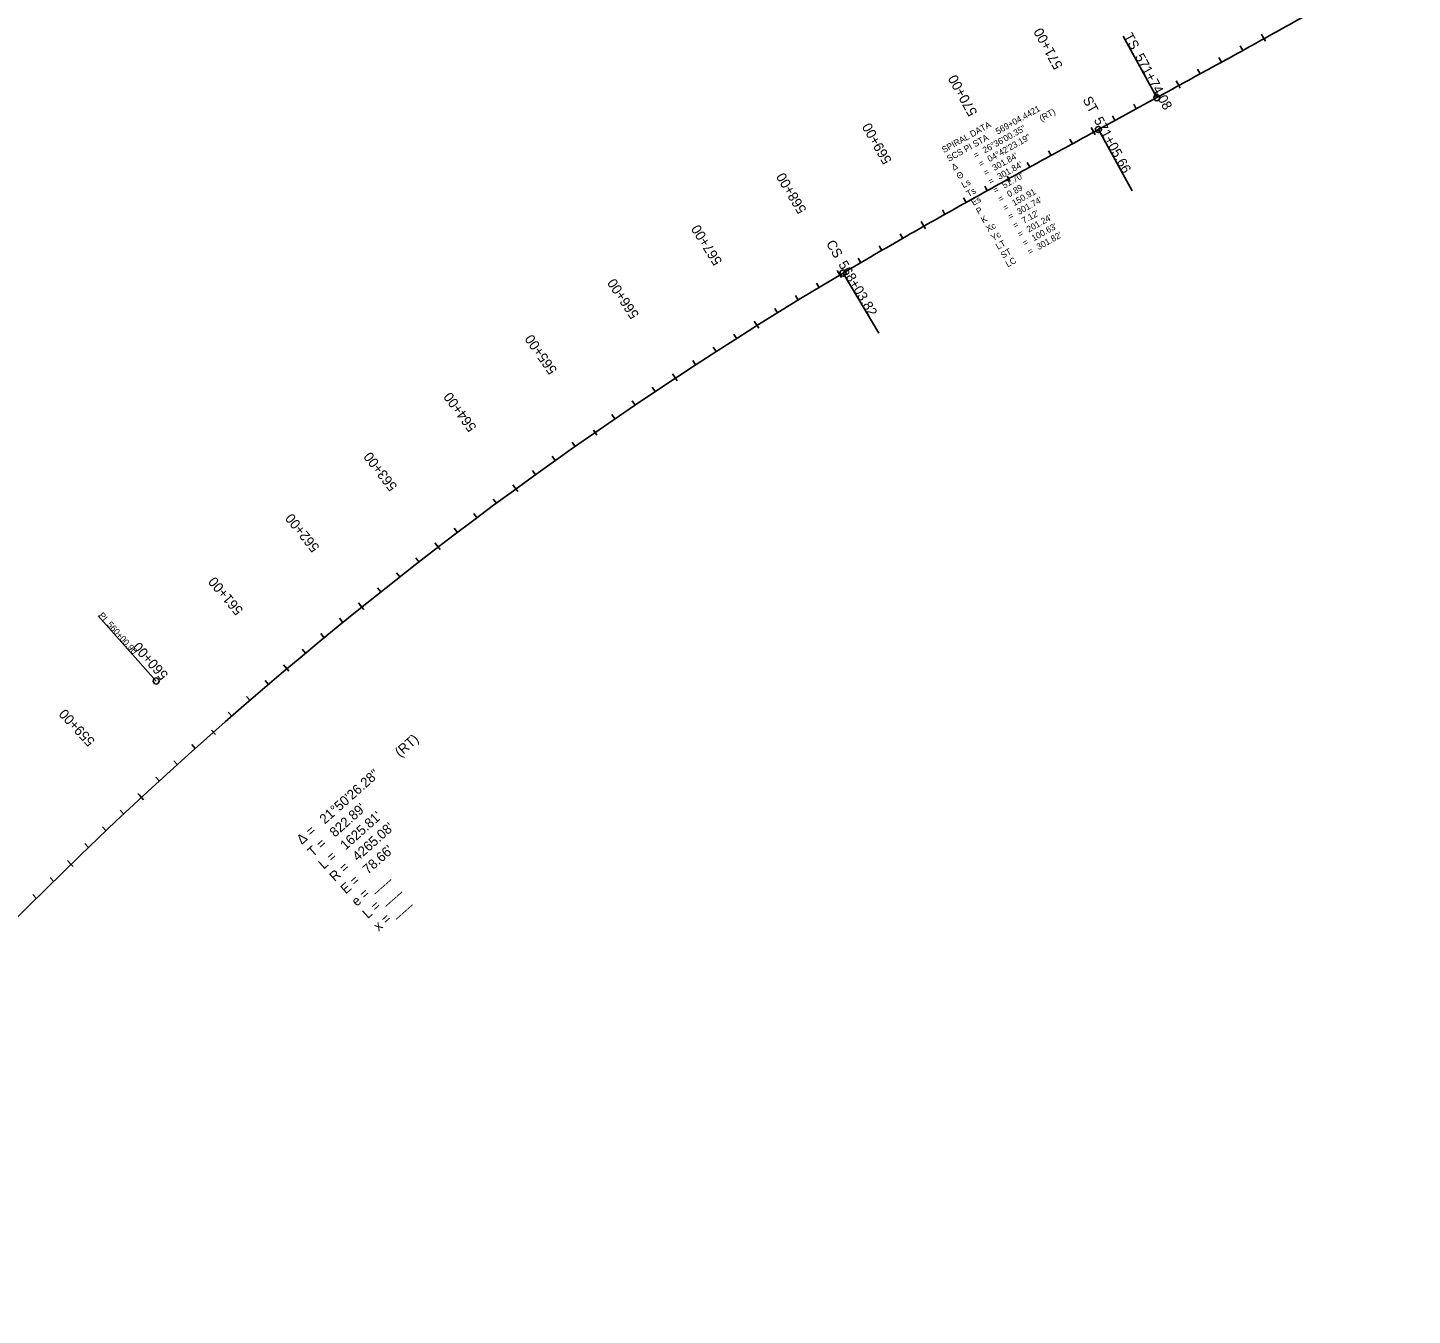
# Model space of a CAD drawing. Extents: x 11276213 to 11292489, y 9492633 to 9513914.
# Drawn here: x 11283838 to 11285264, y 9501955 to 9503281 of the extents above; entities that cross this region are included whole.
import ezdxf

# ---------------------------------------------------------------- set-up
doc = ezdxf.new("R2010")
doc.units = 0
for name, color, linetype in [('Alignment', 7, 'Continuous'), ('TextAlignment', 7, 'Continuous'), ('TextAlignmentLrg', 7, 'Continuous'), ('TextAlignmentSml', 7, 'Continuous')]:
    doc.layers.add(name, color=color, linetype=linetype)

msp = doc.modelspace()

# ---------------------------------------------------------------- linework, layer by layer
at = {"layer": 'Alignment'}
msp.add_line((11284940.5, 9503176.6), (11285000.6, 9503209.4), dxfattribs=at)
msp.add_arc((11286854.8, 9499361.3), 4265.1, 120.6982, 142.5389, dxfattribs=at)
for points in [[(11285000.6, 9503209.4), (11285022.6, 9503221.5), (11285066.8, 9503245.6), (11285132.8, 9503282.1), (11285198.6, 9503319.1), (11285242.1, 9503344.3), (11285263.8, 9503357.1)], [(11284677.4, 9503028.7), (11284699.1, 9503041.5), (11284742.5, 9503066.8), (11284808.3, 9503103.9), (11284874.3, 9503140.4), (11284918.5, 9503164.5), (11284940.5, 9503176.6)]]:
    msp.add_open_spline(points, degree=3, dxfattribs=at)
at = {"layer": 'TextAlignment'}
for p, q in [((11285000.6, 9503209.4), (11284966, 9503272.6)), ((11284940.5, 9503176.6), (11285000.6, 9503209.4)), ((11284940.5, 9503176.6), (11284975.1, 9503113.4)), ((11284677.4, 9503028.7), (11284714.2, 9502966.7)), ((11284677.4, 9503028.7), (11284714.2, 9502966.7)), ((11283969.9, 9502608.6), (11283910.1, 9502675.8))]:
    msp.add_line(p, q, dxfattribs=at)
for centre in [(11285000.6, 9503209.4), (11284940.5, 9503176.6), (11284677.4, 9503028.7), (11284677.4, 9503028.7), (11283969.9, 9502608.6)]:
    msp.add_circle(centre, 3.12, dxfattribs=at)
msp.add_arc((11286854.8, 9499361.3), 4265.1, 120.6982, 142.5389, dxfattribs=at)
for points in [[(11285000.6, 9503209.4), (11285022.6, 9503221.5), (11285066.8, 9503245.6), (11285132.8, 9503282.1), (11285198.6, 9503319.1), (11285242.1, 9503344.3), (11285263.8, 9503357.1)], [(11284677.4, 9503028.7), (11284699.1, 9503041.5), (11284742.5, 9503066.8), (11284808.3, 9503103.9), (11284874.3, 9503140.4), (11284918.5, 9503164.5), (11284940.5, 9503176.6)]]:
    msp.add_open_spline(points, degree=3, dxfattribs=at)
at = {"layer": 'TextAlignmentLrg'}
for p, q in [((11285110.9, 9503270), (11285108.3, 9503274.8)), ((11285023.3, 9503221.8), (11285020.7, 9503226.6)), ((11284935.6, 9503173.9), (11284933, 9503178.7)), ((11284846.4, 9503128.4), (11284849.4, 9503123.1)), ((11284760.6, 9503076.9), (11284757.9, 9503081.7)), ((11284674.2, 9503026.7), (11284671.4, 9503031.4)), ((11284588.8, 9502974.6), (11284585.9, 9502979.2)), ((11284504.7, 9502920.5), (11284501.7, 9502925)), ((11284420.2, 9502866.9), (11284423.7, 9502861.9)), ((11284340.5, 9502806.4), (11284337.3, 9502810.8)), ((11284260.4, 9502746.5), (11284257.1, 9502750.8)), ((11284181.8, 9502684.7), (11284178.3, 9502689)), ((11284104.6, 9502621.2), (11284101.1, 9502625.3)), ((11284026.9, 9502558.1), (11284030.9, 9502553.5)), ((11283954.8, 9502488.7), (11283951.1, 9502492.7)), ((11283882.3, 9502419.8), (11283878.5, 9502423.7))]:
    msp.add_line(p, q, dxfattribs=at)
at = {"layer": 'TextAlignmentSml'}
for p, q in [((11285089.1, 9503257.9), (11285086.4, 9503262.7)), ((11285109.5, 9503272.7), (11285112.4, 9503267.4)), ((11285067.2, 9503245.9), (11285064.5, 9503250.7)), ((11285045.2, 9503233.9), (11285042.6, 9503238.6)), ((11285021.8, 9503224.5), (11285024.8, 9503219.2)), ((11285001.4, 9503209.8), (11284998.8, 9503214.6)), ((11284957.5, 9503185.9), (11284954.9, 9503190.6)), ((11284979.4, 9503197.9), (11284976.8, 9503202.6)), ((11284934.1, 9503176.5), (11284937, 9503171.2)), ((11284913.6, 9503161.9), (11284911, 9503166.7)), ((11284891.7, 9503149.9), (11284889.1, 9503154.6)), ((11284869.8, 9503137.8), (11284867.2, 9503142.6)), ((11284826, 9503113.6), (11284823.4, 9503118.4)), ((11284846.4, 9503128.4), (11284849.4, 9503123.1)), ((11284804.2, 9503101.5), (11284801.5, 9503106.2)), ((11284782.4, 9503089.2), (11284779.7, 9503094)), ((11284759.1, 9503079.6), (11284762.2, 9503074.3)), ((11284738.9, 9503064.5), (11284736.2, 9503069.3)), ((11284717.3, 9503052), (11284714.5, 9503056.8)), ((11284695.7, 9503039.4), (11284692.9, 9503044.1)), ((11284652.7, 9503013.9), (11284649.9, 9503018.5)), ((11284672.6, 9503029.3), (11284675.7, 9503024.1)), ((11284631.3, 9503000.9), (11284628.5, 9503005.6)), ((11284610, 9502987.8), (11284607.2, 9502992.4)), ((11284587.2, 9502977.2), (11284590.5, 9502972)), ((11284567.7, 9502961.2), (11284564.8, 9502965.8)), ((11284546.6, 9502947.8), (11284543.7, 9502952.4)), ((11284525.6, 9502934.2), (11284522.7, 9502938.7)), ((11284503.1, 9502923), (11284506.4, 9502917.9)), ((11284483.9, 9502906.6), (11284480.9, 9502911.2)), ((11284463.2, 9502892.7), (11284460.1, 9502897.2)), ((11284442.5, 9502878.6), (11284439.4, 9502883.1)), ((11284420.2, 9502866.9), (11284423.7, 9502861.9)), ((11284401.5, 9502850.1), (11284398.3, 9502854.5)), ((11284381, 9502835.6), (11284377.9, 9502840.1)), ((11284360.7, 9502821.1), (11284357.5, 9502825.5)), ((11284338.7, 9502808.9), (11284342.3, 9502803.9)), ((11284320.3, 9502791.6), (11284317.1, 9502796)), ((11284300.3, 9502776.7), (11284297, 9502781)), ((11284280.3, 9502761.6), (11284277, 9502766)), ((11284258.5, 9502748.9), (11284262.3, 9502744.1)), ((11284240.6, 9502731.2), (11284237.3, 9502735.5)), ((11284220.9, 9502715.8), (11284217.5, 9502720.1)), ((11284201.3, 9502700.3), (11284197.9, 9502704.6)), ((11284179.8, 9502687.1), (11284183.7, 9502682.4)), ((11284162.3, 9502669), (11284158.9, 9502673.2)), ((11284143, 9502653.2), (11284139.5, 9502657.4)), ((11284123.7, 9502637.2), (11284120.2, 9502641.4)), ((11284102.6, 9502623.5), (11284106.6, 9502618.8)), ((11284085.5, 9502605), (11284082, 9502609.1)), ((11284066.6, 9502588.7), (11284063, 9502592.8)), ((11284047.7, 9502572.3), (11284044.1, 9502576.4)), ((11284026.9, 9502558.1), (11284030.9, 9502553.5)), ((11284010.2, 9502539.2), (11284006.6, 9502543.2)), ((11283991.7, 9502522.4), (11283988, 9502526.5)), ((11283973.2, 9502505.6), (11283969.5, 9502509.6)), ((11283952.7, 9502490.9), (11283956.9, 9502486.4)), ((11283936.5, 9502471.6), (11283932.8, 9502475.6)), ((11283918.3, 9502454.4), (11283914.6, 9502458.4)), ((11283900.2, 9502437.2), (11283896.5, 9502441.1)), ((11283880.1, 9502422), (11283884.4, 9502417.6)), ((11283864.4, 9502402.3), (11283860.6, 9502406.2)), ((11283846.6, 9502384.7), (11283842.8, 9502388.6))]:
    msp.add_line(p, q, dxfattribs=at)

# ---------------------------------------------------------------- texts
at = {"layer": 'TextAlignment'}
for s, height, rotation, p in [('TS', 10.02, 298.6708, (11284966.2, 9503272.7)), ('571+74.08', 10.02, 298.6708, (11284977.7, 9503251.6)), ('ST', 10.02, 298.6708, (11284923.9, 9503207.4)), ('569+04.4421', 6.48, 29.1777, (11284836.8, 9503171.3)), (' (RT)', 6.48, 29.1777, (11284879.7, 9503183.4)), ('571+05.66', 10.02, 298.6708, (11284935.4, 9503186.3)), ('SPIRAL DATA', 6.48, 29.1777, (11284781.3, 9503152.2)), ('26°36\'00.35"', 6.48, 29.1777, (11284823.3, 9503151.9)), ('SCS PI STA ', 6.48, 29.1777, (11284786.4, 9503143.1)), ('04°42\'23.19"', 6.48, 29.1777, (11284828.3, 9503142.8)), ('= ', 6.48, 29.1777, (11284814, 9503146.7)), ("301.84'", 6.48, 29.1777, (11284833.4, 9503133.8)), ('Δ', 6.48, 29.1777, (11284791.4, 9503134.1)), ('Θ ', 6.48, 29.1777, (11284796.5, 9503125)), ('= ', 6.48, 29.1777, (11284819.1, 9503137.7)), ('= ', 6.48, 29.1777, (11284824.2, 9503128.6)), ("301.84'", 6.48, 29.1777, (11284838.4, 9503124.7)), ("51.70'", 6.48, 29.1777, (11284843.5, 9503115.7)), ('Ls', 6.48, 29.1777, (11284801.5, 9503116)), ('= ', 6.48, 29.1777, (11284829.2, 9503119.6)), ('0.89', 6.48, 29.1777, (11284848.5, 9503106.6)), ('Ts', 6.48, 29.1777, (11284806.6, 9503106.9)), ('Es', 6.48, 29.1777, (11284811.6, 9503097.9)), ('= ', 6.48, 29.1777, (11284834.3, 9503110.5)), ('= ', 6.48, 29.1777, (11284839.3, 9503101.5)), ('150.91', 6.48, 29.1777, (11284853.6, 9503097.6)), ("301.74'", 6.48, 29.1777, (11284858.6, 9503088.5)), ('P', 6.48, 29.1777, (11284816.7, 9503088.8)), ('= ', 6.48, 29.1777, (11284844.4, 9503092.4)), ('= ', 6.48, 29.1777, (11284849.4, 9503083.4)), ("7.12'", 6.48, 29.1777, (11284863.7, 9503079.4)), ('K', 6.48, 29.1777, (11284821.7, 9503079.8)), ('Xc', 6.48, 29.1777, (11284826.8, 9503070.7)), ('= ', 6.48, 29.1777, (11284854.5, 9503074.3)), ("201.24'", 6.48, 29.1777, (11284868.7, 9503070.4)), ("100.63'", 6.48, 29.1777, (11284873.8, 9503061.3)), ('CS', 10.02, 300.6982, (11284659.6, 9503059.1)), ('CS', 10.02, 300.6982, (11284659.6, 9503059.1)), ('Yc', 6.48, 29.1777, (11284831.9, 9503061.7)), ('LT', 6.48, 29.1777, (11284836.9, 9503052.6)), ('= ', 6.48, 29.1777, (11284859.5, 9503065.3)), ('= ', 6.48, 29.1777, (11284864.6, 9503056.2)), ("301.82'", 6.48, 29.1777, (11284878.9, 9503052.3)), ('ST ', 6.48, 29.1777, (11284842, 9503043.6)), ('= ', 6.48, 29.1777, (11284869.6, 9503047.2)), ('568+03.82', 10.02, 300.6982, (11284672.2, 9503037.8)), ('568+03.82', 10.02, 300.6982, (11284672.2, 9503037.8)), ('LC', 6.48, 29.1777, (11284847, 9503034.5)), ('PI ', 6.48, 311.6185, (11283910.2, 9502675.9)), ('560+00.90', 6.48, 311.6185, (11283918.8, 9502666.3)), (' (RT)', 10.02, 41.6185, (11284218.4, 9502527.2)), ('21°50\'26.28"', 10.02, 41.6185, (11284143.6, 9502460.7)), ("822.89'", 10.02, 41.6185, (11284154, 9502447.2)), ("1625.81'", 10.02, 41.6185, (11284164.9, 9502434)), ("4265.08'", 10.02, 41.6185, (11284177.5, 9502422.5)), ('Δ = ', 10.02, 41.6185, (11284119.9, 9502439.7)), ('T = ', 10.02, 41.6185, (11284131.2, 9502426.9)), ("78.66'", 10.02, 41.6185, (11284188, 9502409)), ('L = ', 10.02, 41.6185, (11284142.5, 9502414.2)), ('R = ', 10.02, 41.6185, (11284153.8, 9502401.5)), ('E = ', 10.02, 41.6185, (11284165.2, 9502388.7)), ('e = ___ ', 10.02, 41.6185, (11284176.5, 9502376)), ('L = ___', 10.02, 41.6185, (11284187.8, 9502363.3)), ('x = ___', 10.02, 41.6185, (11284199.1, 9502350.5))]:
    msp.add_text(s, height=height, rotation=rotation, dxfattribs=at).set_placement(p)
at = {"layer": 'TextAlignmentLrg'}
for s, rotation, p in [('570+00', 118.9192, (11284816.1, 9503193.9)), ('565+00', 124.7796, (11284383.4, 9502928.9)), ('560+00', 131.4965, (11283983, 9502615.3))]:
    msp.add_text(s, height=10.2, rotation=rotation, dxfattribs=at).set_placement(p)
at = {"layer": 'TextAlignmentSml'}
for s, rotation, p in [('571+00', 118.6715, (11284904.1, 9503242.1)), ('570+00', 118.9192, (11284816.1, 9503193.9)), ('569+00', 119.612, (11284728, 9503144.6)), ('568+00', 120.7495, (11284640.2, 9503093.8)), ('567+00', 122.0929, (11284553.3, 9503040.8)), ('566+00', 123.4362, (11284467.7, 9502985.9)), ('565+00', 124.7796, (11284383.4, 9502928.9)), ('564+00', 126.123, (11284300.4, 9502870)), ('563+00', 127.4663, (11284218.8, 9502809.1)), ('562+00', 128.8097, (11284138.7, 9502746.4)), ('561+00', 130.1531, (11284060.1, 9502681.8)), ('560+00', 131.4965, (11283983, 9502615.3)), ('559+00', 132.8398, (11283907.5, 9502547.1))]:
    msp.add_text(s, height=10.2, rotation=rotation, dxfattribs=at).set_placement(p)

doc.saveas('drawing.dxf')
